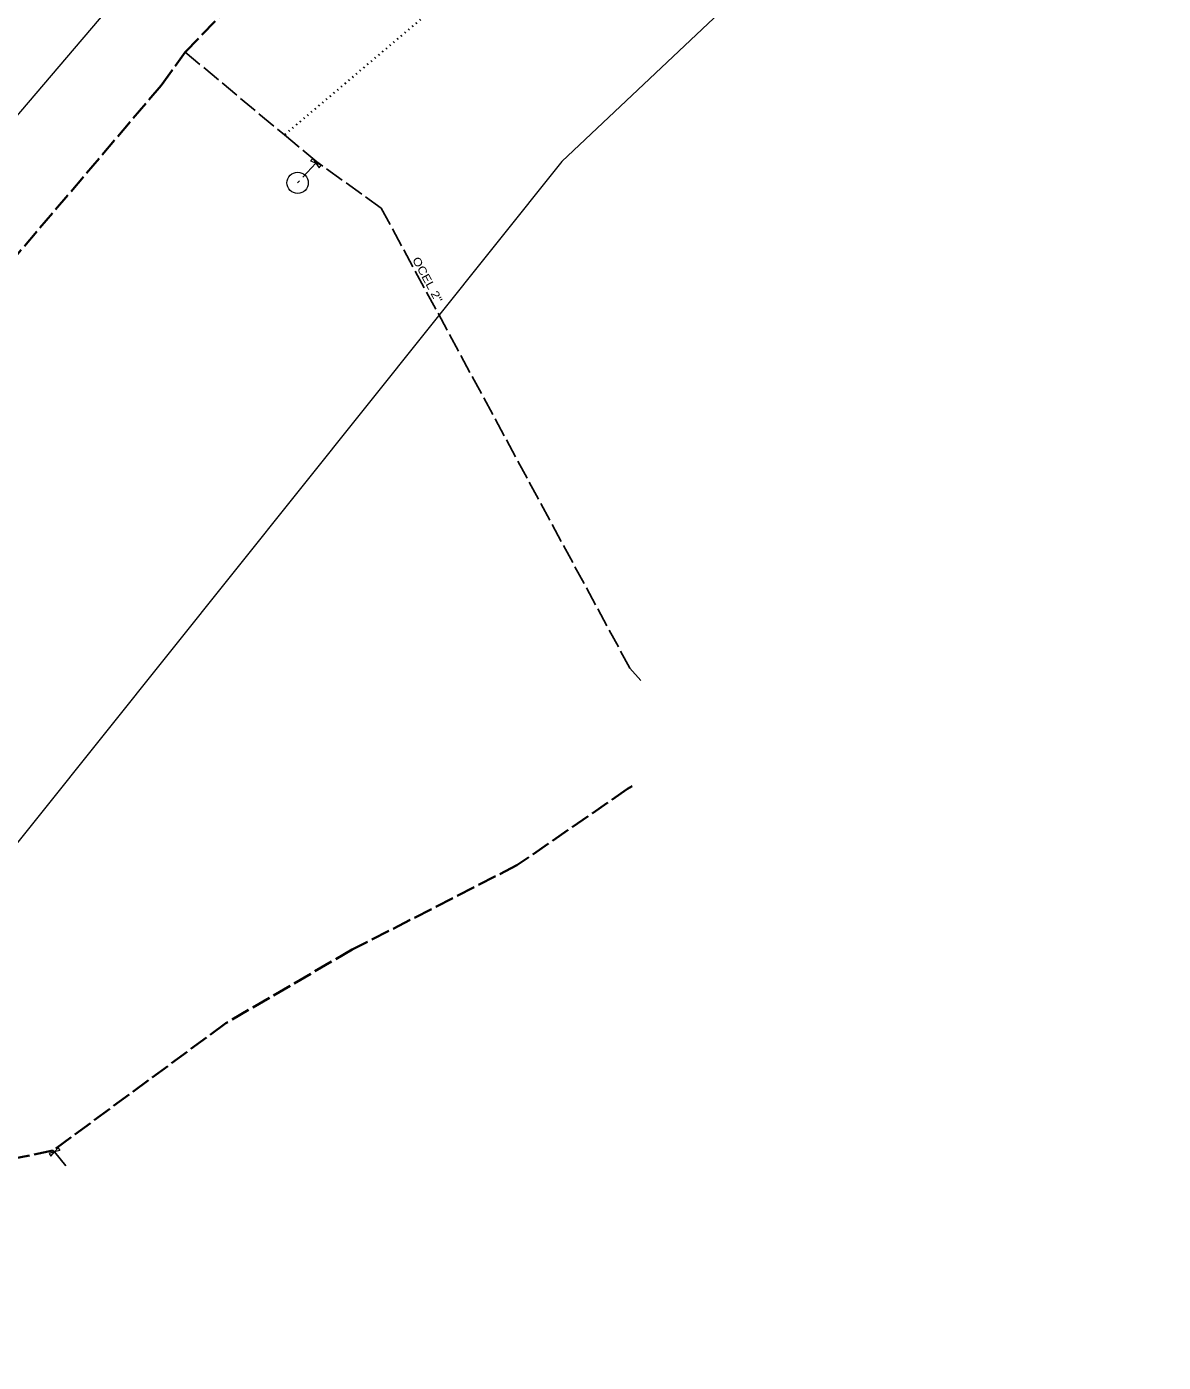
# Model space of a CAD drawing. Extents: x -616592 to -615844, y -1088988 to -1088174.
# Drawn here: x -616252.5 to -616145.9, y -1088630.7 to -1088505.5 of the extents above; entities that cross this region are included whole.
import ezdxf
from ezdxf.enums import TextEntityAlignment as Align

# ---------------------------------------------------------------- set-up
doc = ezdxf.new("R2010")
doc.units = 0
doc.header["$LTSCALE"] = 0.3
for name, pattern in [('DOTTED', [1.5, 0.3, -1.2]), ('LONG_DASHED', [7.5, 6, -1.5]), ('SHORT_DASHED', [2.7, 1.5, -1.2])]:
    doc.linetypes.add(name, pattern=pattern)
for name, color, linetype, lineweight in [('1', 7, 'Continuous', 13), ('10', 7, 'Continuous', 13), ('35', 7, 'LONG_DASHED', 35), ('36', 7, 'SHORT_DASHED', 35), ('50', 7, 'LONG_DASHED', 25)]:
    doc.layers.add(name, color=color, linetype=linetype, lineweight=lineweight)
doc.layers.add('16', color=7, linetype='Continuous')

msp = doc.modelspace()

# ---------------------------------------------------------------- linework, layer by layer
at = {"layer": '1'}
msp.add_lwpolyline([(-616317.402, -1088743.479), (-616316.925, -1088623.142), (-616336.026, -1088584.94), (-616318.357, -1088562.497), (-616286.363, -1088552.469), (-616214.734, -1088468.424), (-616144.06, -1088425.447), (-616043.302, -1088392.02), (-615921.533, -1088342.835), (-615901, -1088273.116), (-615900.045, -1088185.251), (-615900.045, -1088185.251), (-615851.337, -1088190.027), (-615863.753, -1088293.172), (-615879.033, -1088367.189), (-615932.994, -1088397.75), (-616036.139, -1088431.177), (-616143.105, -1088462.216), (-616202.318, -1088518.087), (-616257.711, -1088587.328), (-616274.902, -1088683.788)], dxfattribs=at)
at = {"layer": '10'}
for points in [[(-616225.383, -1088518.246), (-616225.867, -1088518.051), (-616225.68, -1088517.817), (-616225.383, -1088518.246), (-616225.086, -1088518.675), (-616224.899, -1088518.441)], [(-616249.907, -1088610.942), (-616249.568, -1088610.545), (-616249.405, -1088610.797), (-616249.907, -1088610.942), (-616250.409, -1088611.087), (-616250.246, -1088611.339)]]:
    msp.add_lwpolyline(points, close=True, dxfattribs=at)
msp.add_circle((-616227.101, -1088520.092), 1, dxfattribs=at)
at = {"layer": '35'}
msp.add_line((-616258.554, -1088532.884), (-616239.896, -1088510.962), dxfattribs=at)
for points in [[(-616239.896, -1088510.962), (-616237.64, -1088507.853), (-616224.248, -1088493.884)], [(-616195.747, -1088576.653), (-616196.171, -1088576.902), (-616206.541, -1088584.064), (-616221.975, -1088591.965), (-616233.849, -1088598.88), (-616250.043, -1088610.816)], [(-616250.043, -1088610.816), (-616257.588, -1088612.33), (-616263.226, -1088611.964)]]:
    msp.add_lwpolyline(points, dxfattribs=at)
at = {"layer": '36', "linetype": 'DOTTED'}
msp.add_line((-616178.737, -1088473.552), (-616228.34, -1088515.6), dxfattribs=at)
at = {"layer": '50'}
for points in [[(-616237.64, -1088507.853), (-616228.34, -1088515.6), (-616225.3, -1088518.133)], [(-616225.3, -1088518.133), (-616225.383, -1088518.246), (-616227.101, -1088520.092)], [(-616194.929, -1088566.751), (-616195.963, -1088565.575), (-616219.27, -1088522.465), (-616225.3, -1088518.133)], [(-616250.043, -1088610.816), (-616249.907, -1088610.942), (-616248.849, -1088612.249)]]:
    msp.add_lwpolyline(points, dxfattribs=at)

# ---------------------------------------------------------------- texts
at = {"layer": '16', "width": 1.2}
msp.add_text('OCEL 2"', height=0.75, rotation=298.397, dxfattribs=at).set_placement((-616215.2594, -1088529.3577), align=Align.CENTER)

doc.saveas('drawing.dxf')
